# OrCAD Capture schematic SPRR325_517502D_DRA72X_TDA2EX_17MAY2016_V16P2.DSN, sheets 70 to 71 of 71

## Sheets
70 SH28 - MUX A/C QSPI/EMMC/GPMX: size B; rev: A
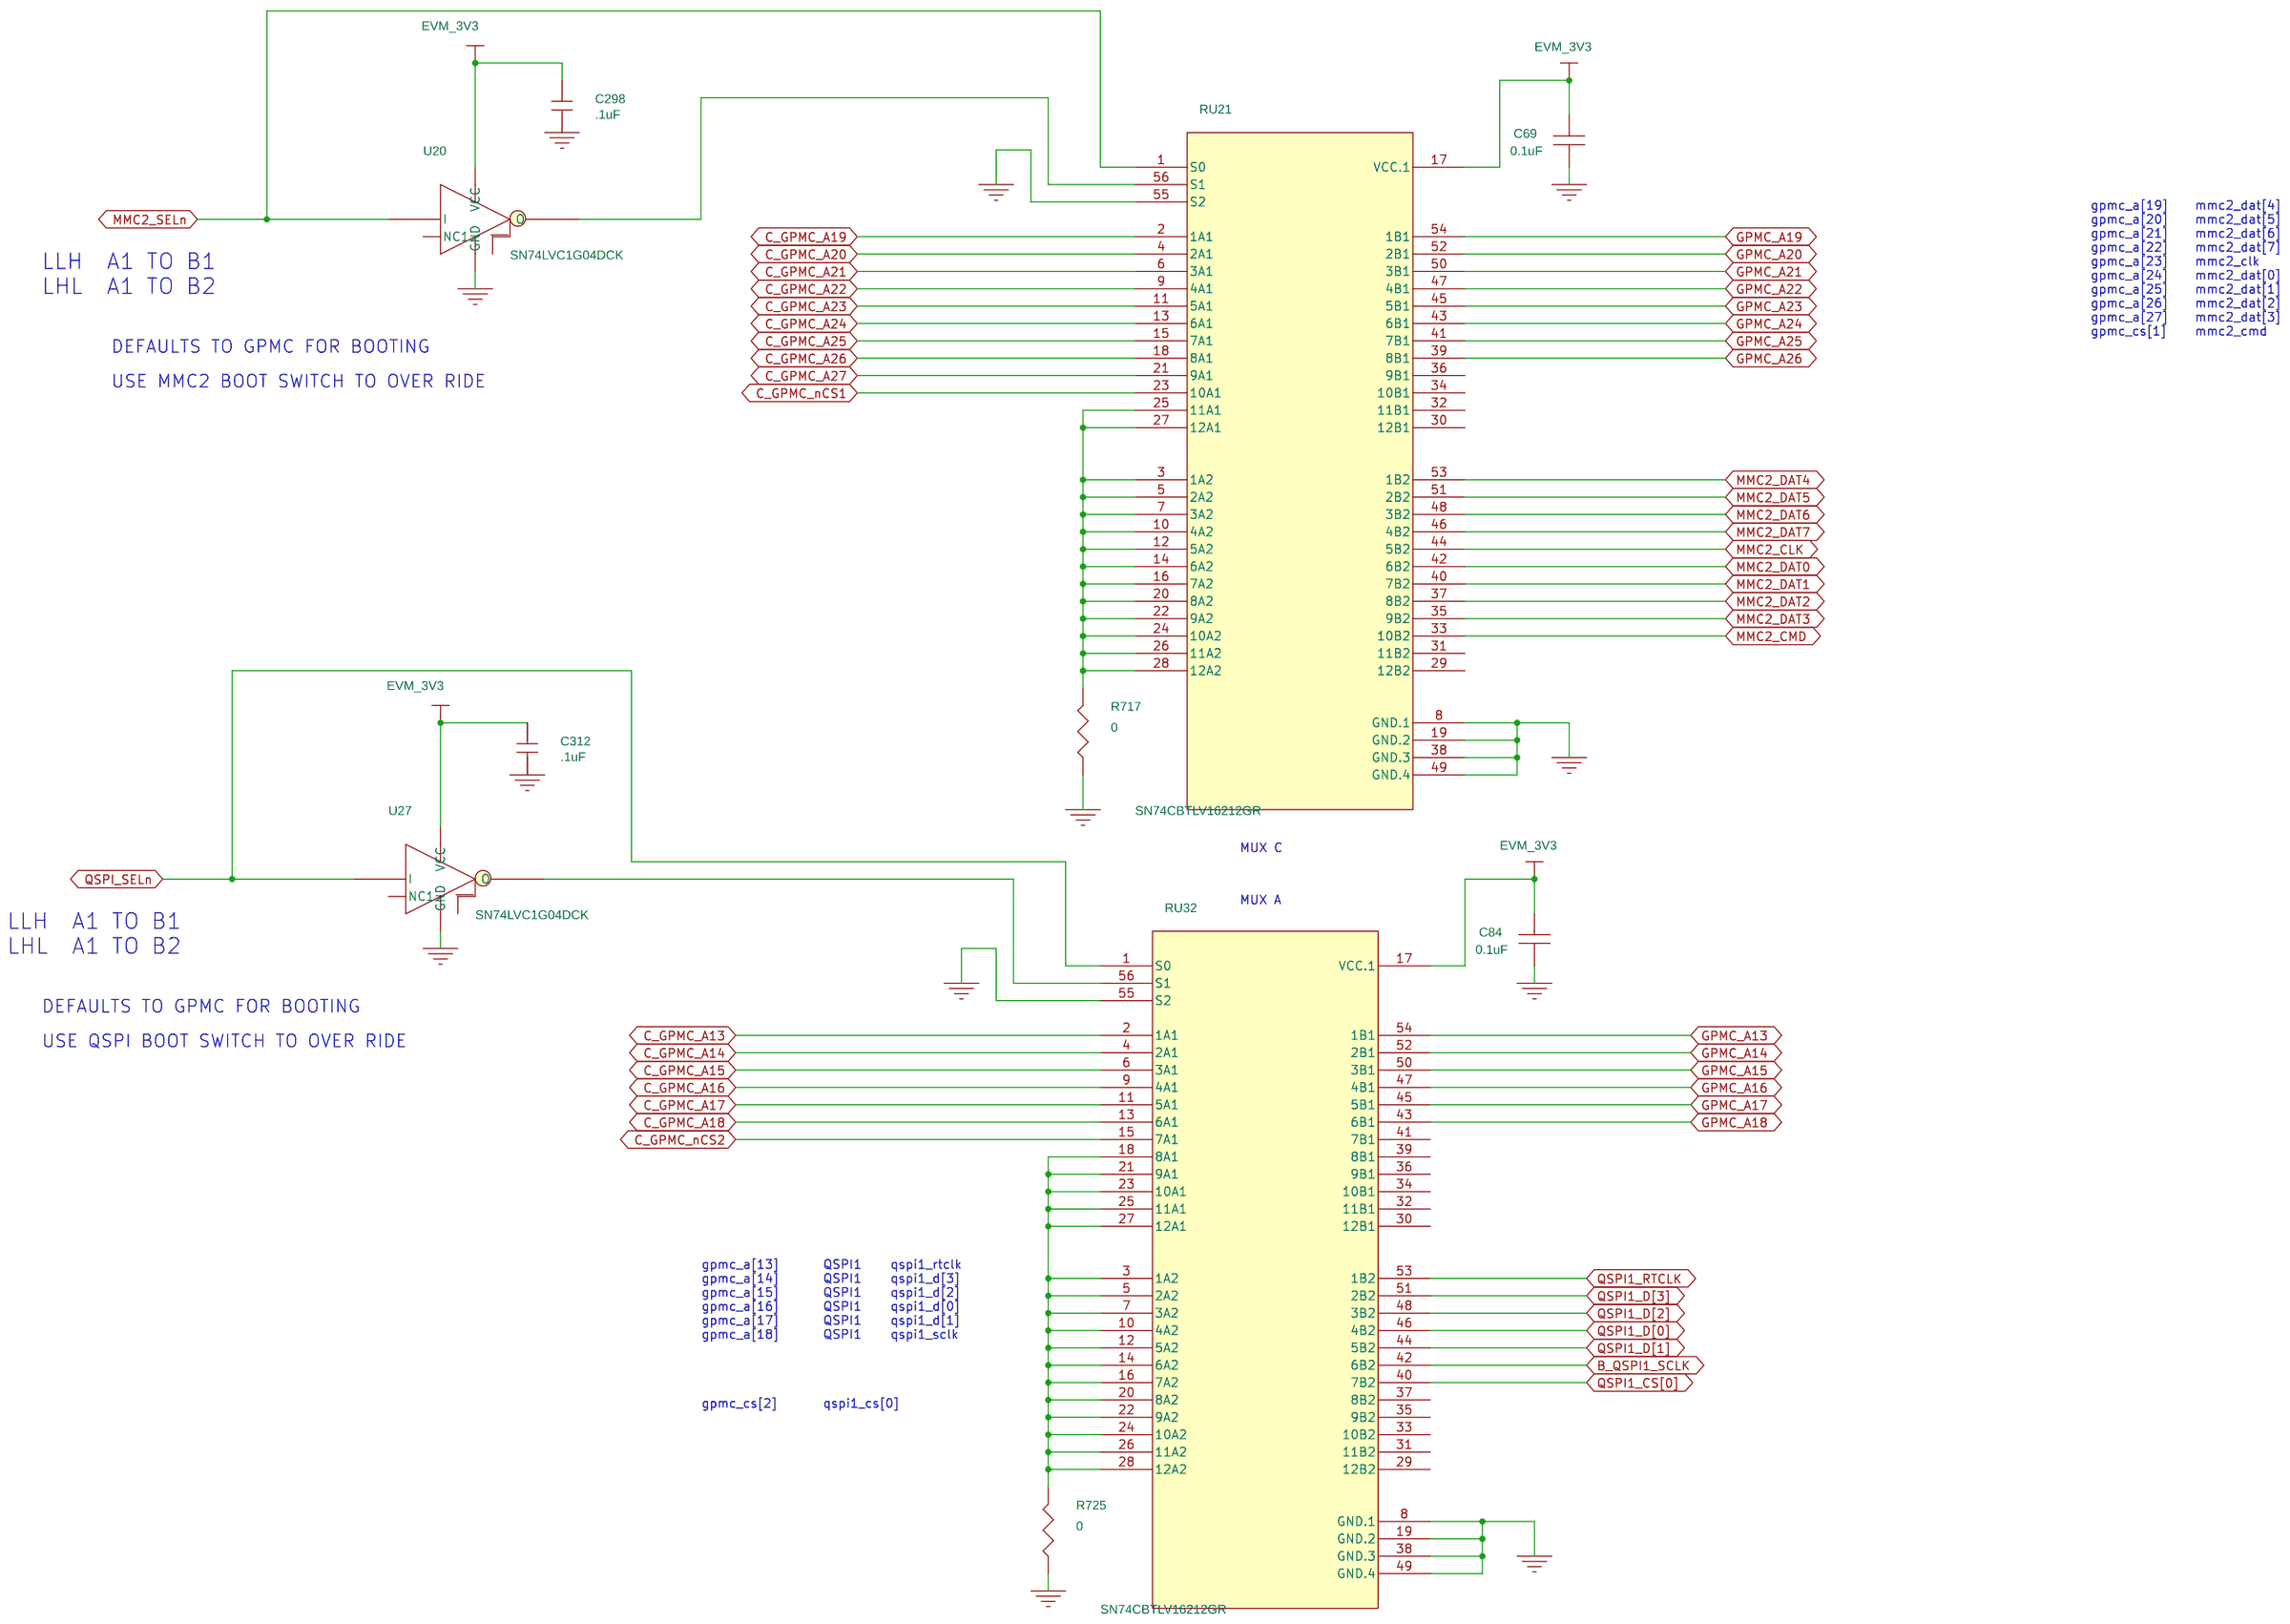
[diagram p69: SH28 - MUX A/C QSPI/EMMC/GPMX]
71 SH13 - SoC SATA/PCIe INTERFACE: size B; rev: C
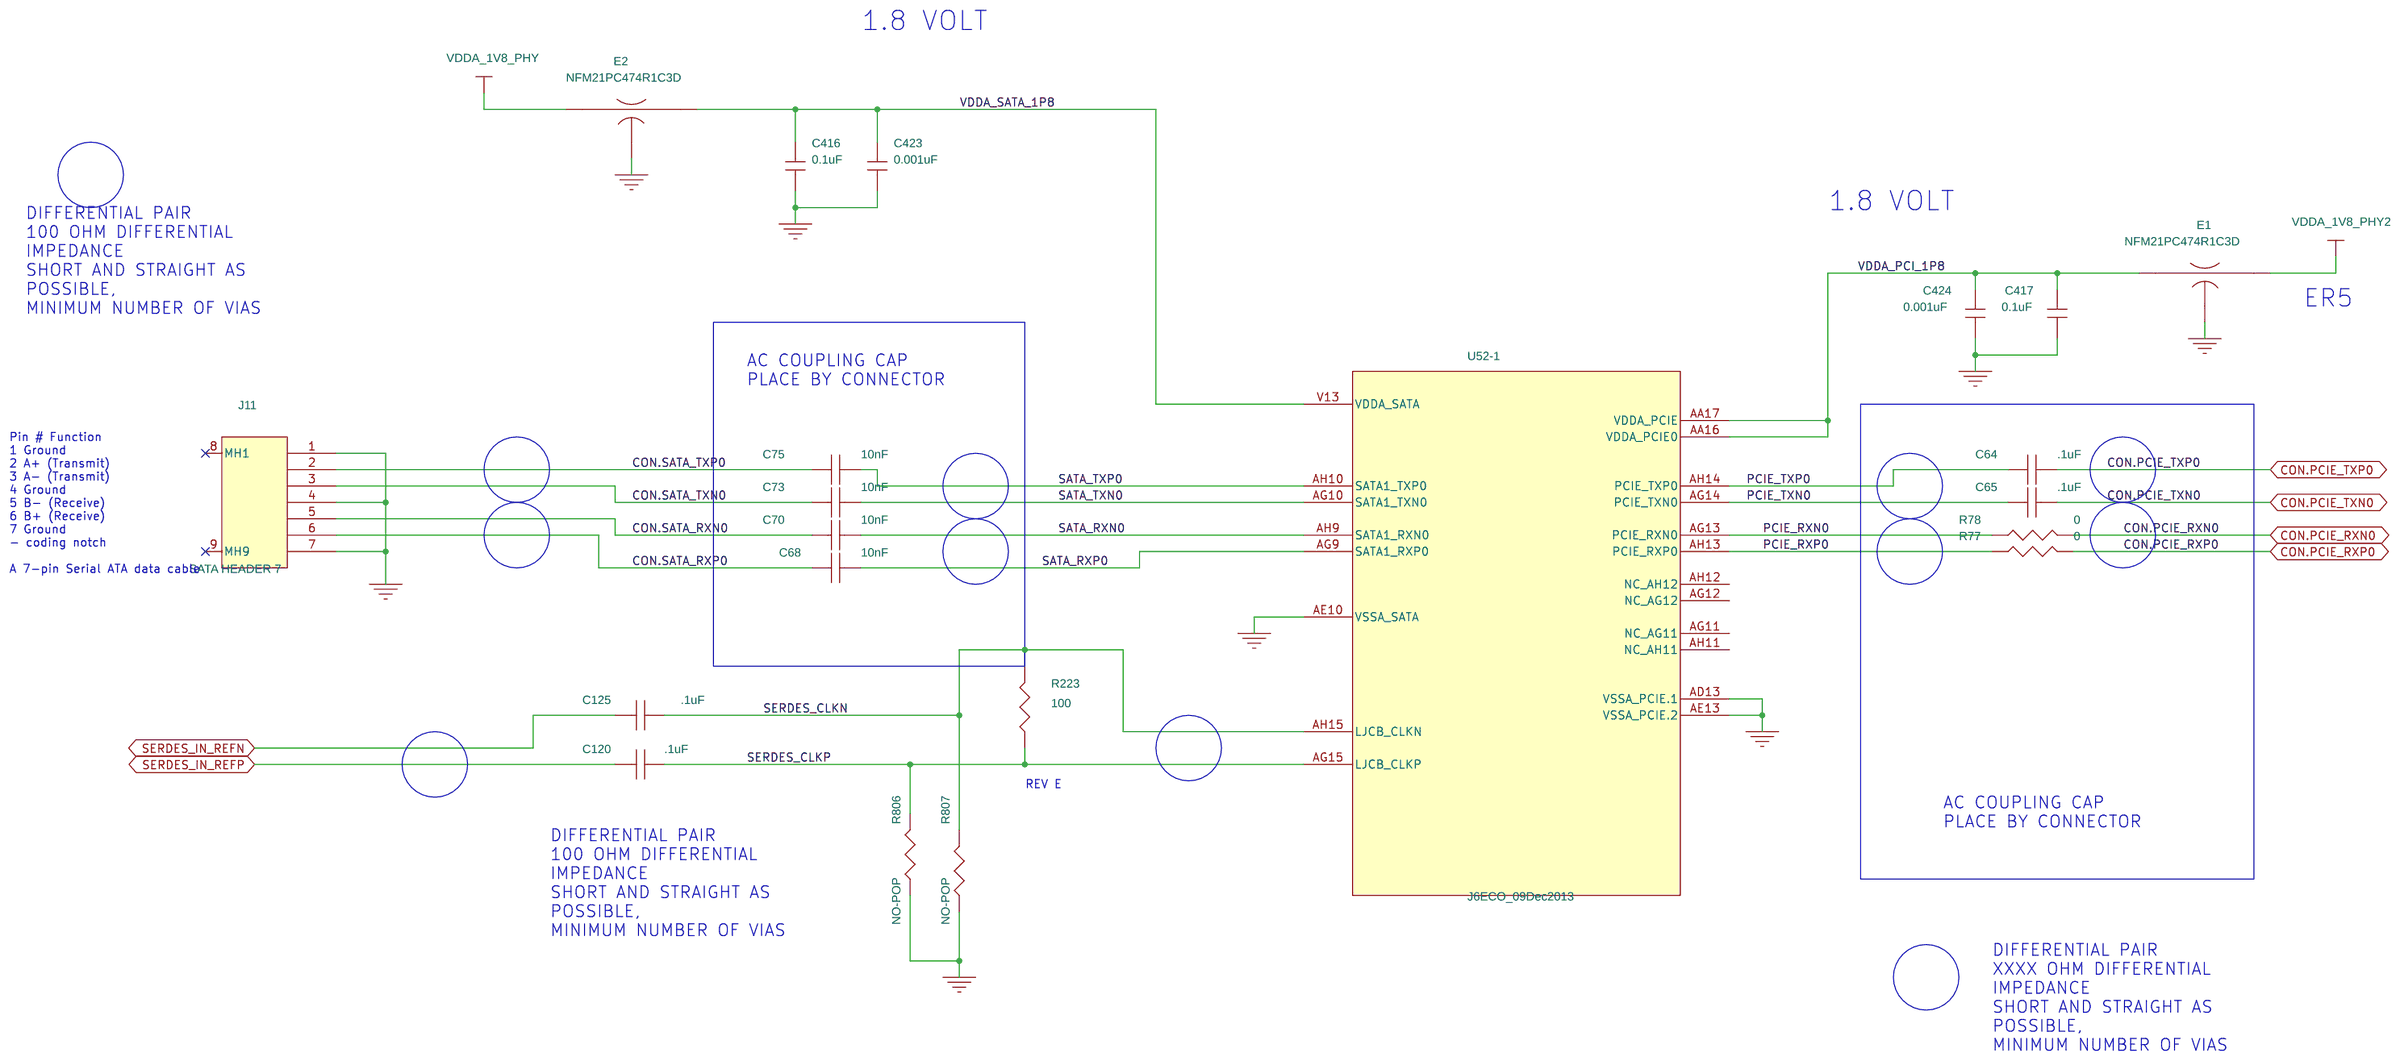
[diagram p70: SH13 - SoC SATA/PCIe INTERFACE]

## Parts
sheet SH13 - SoC SATA/PCIe INTERFACE
C64  .1uF  [c402-25]
C65  .1uF  [c402-25]
C68  10nF  [c402-25]
C70  10nF  [c402-25]
C73  10nF  [c402-25]
C75  10nF  [c402-25]
C120  .1uF  [c603-35x45]
C125  .1uF  [c603-35x45]
C416  0.1uF  [c201-18p5x15]
C417  0.1uF  [c201-18p5x15]
C423  0.001uF  [c201-18p5x15]
C424  0.001uF  [c201-18p5x15]
E1  NFM21PC474R1C3D  [emi-NFM21p]
E2  NFM21PC474R1C3D  [emi-NFM21p]
J11  SATA HEADER 7  [molex-67491-002]
R77  0  [r402-25]
R78  0  [r402-25]
R223  100  [r402-25]
R806  NO-POP  [r201-6p6spc]
R807  NO-POP  [r201-6p6spc]
sheet SH17 - SoC IO POWER
U52  J6ECO_09Dec2013  [sktbga-zkk-6334-p760]  (sections -1,-10,-11,-12,-13,-14,-15,-16,-17,-18,-19,-2,-20,-21,-22,-23,-3,-4,-5,-6,-7,-8,-9)
sheet SH28 - MUX A/C QSPI/EMMC/GPMX
C69  0.1uF  [c402-25]
C84  0.1uF  [c402-25]
C298  .1uF  [c402-25]
C312  .1uF  [c402-25]
R717  0  [r201-6p6spc]
R725  0  [r201-6p6spc]
RU21  SN74CBTLV16212GR  [dgg56-12x80]
RU32  SN74CBTLV16212GR  [dgg56-12x80]
U20  SN74LVC1G04DCK  [dck-5]
U27  SN74LVC1G04DCK  [dck-5]

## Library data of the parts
C64 C65 = CAP_.1_uF_10%_0603: Part #: 101587-1100R
C68 C70 C73 C75 = CAP_.1_uF_10%_0603: Part #: 101587-1101R
C120 C125 = CAP_.1_uF_10%_0603: Part #: 100994-1100R
C416 C417 = CAP_NP: Part #: 103241-1100R
C423 C424 = CAP_NP: Part #: 103367-1102R
E1 E2 = NFM_1: Part #: 102569-1470R
J11 = HEADER_7_0: Part #: 102930-0007R
R77 R78 = R: Part #: 101370-0001R
R223 = R: Part #: 101370-1001R
R806 R807 = R: Part #: R0201-NOPOP
U52 = J6ECO_RevC_0: Part #: 104492-0002R-TI
C69 C84 = CAP: Part #: 101587-1100R
C298 C312 = CAP_NP: Part #: 101587-1100R
R717 R725 = R: Part #: 103158-0001R
RU21 RU32 = SN74CBT16212DGGR_0: Part #: 102693-0001R
U20 U27 = SN74LVC1GU04_1: Part #: 101057-0004R

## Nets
GND: C69.2 C84.2 C298.2 C312.2 C416.2 C417.2 C423.2 C424.2 E1.2 E2.2 J11.1 J11.4 J11.7 R717.1 R725.1 R806.2 R807.2 RU21.8(GND.1) RU21.19(GND.2) RU21.38(GND.3) RU21.49(GND.4) RU21.55(S2) RU32.8(GND.1) RU32.19(GND.2) RU32.38(GND.3) RU32.49(GND.4) RU32.55(S2) U20.3(GND) U27.3(GND) U52.AD13(VSSA_PCIE.1) U52.AE10(VSSA_SATA) U52.AE13(VSSA_PCIE.2) ; also on sheet 3 5 7 10 11 12 13 14 15 16 17 18 20 21 22 23 24 25 26 27 28 29 30 31 32 33 34 35 36 37 38 39 40 41 42 43 44 45 46 47 48 49 50 51 52 53 54 55 56 57 58 59 62 63 64 65 66 67 68 69
VDDA_1V8_PHY2: E1.3 ; also on sheet 7 58 64
VDDA_PCI_1P8: C417.1 C424.1 E1.1 U52.AA16(VDDA_PCIE0) U52.AA17(VDDA_PCIE)
VDDA_SATA_1P8: C416.1 C423.1 E2.1 U52.V13(VDDA_SATA)
B_QSPI1_SCLK: RU32.42(6B2) ; also on sheet 26
C_GPMC_A13: RU32.2(1A1) ; also on sheet 4
C_GPMC_A14: RU32.4(2A1) ; also on sheet 4
C_GPMC_A15: RU32.6(3A1) ; also on sheet 4
C_GPMC_A16: RU32.9(4A1) ; also on sheet 4
C_GPMC_A17: RU32.11(5A1) ; also on sheet 4
C_GPMC_A18: RU32.13(6A1) ; also on sheet 4
C_GPMC_A19: RU21.2(1A1) ; also on sheet 4
C_GPMC_A20: RU21.4(2A1) ; also on sheet 4
C_GPMC_A21: RU21.6(3A1) ; also on sheet 4
C_GPMC_A22: RU21.9(4A1) ; also on sheet 4
C_GPMC_A23: RU21.11(5A1) ; also on sheet 4
C_GPMC_A24: RU21.13(6A1) ; also on sheet 4
C_GPMC_A25: RU21.15(7A1) ; also on sheet 4
C_GPMC_A26: RU21.18(8A1) ; also on sheet 4
C_GPMC_A27: RU21.21(9A1) ; also on sheet 4
C_GPMC_nCS1: RU21.23(10A1) ; also on sheet 4
C_GPMC_nCS2: RU32.15(7A1) ; also on sheet 4 24
CON.PCIE_RXN0: R78.2 ; also on sheet 36
CON.PCIE_RXP0: R77.2 ; also on sheet 36
CON.PCIE_TXN0: C65.2 ; also on sheet 36
CON.PCIE_TXP0: C64.2 ; also on sheet 36
CON.SATA_RXN0: C70.1 J11.5
CON.SATA_RXP0: C68.1 J11.6
CON.SATA_TXN0: C73.1 J11.3
CON.SATA_TXP0: C75.1 J11.2
EVM_3V3: C69.1 C84.1 C298.1 C312.1 RU21.17(VCC.1) RU32.17(VCC.1) U20.5(VCC) U27.5(VCC) ; also on sheet 3 4 10 11 24 25 26 27 28 29 30 31 32 33 34 35 36 37 38 39 40 42 43 44 45 46 47 48 49 50 51 55 56 58 59 62 63 65 66 67 69
GPMC_A13: RU32.54(1B1) ; also on sheet 28
GPMC_A14: RU32.52(2B1) ; also on sheet 28
GPMC_A15: RU32.50(3B1) ; also on sheet 28
GPMC_A16: RU32.47(4B1) ; also on sheet 28
GPMC_A17: RU32.45(5B1) ; also on sheet 28
GPMC_A18: RU32.43(6B1) ; also on sheet 28
GPMC_A19: RU21.54(1B1) ; also on sheet 24
GPMC_A20: RU21.52(2B1) ; also on sheet 24
GPMC_A21: RU21.50(3B1) ; also on sheet 24
GPMC_A22: RU21.47(4B1) ; also on sheet 24
GPMC_A23: RU21.45(5B1) ; also on sheet 24
GPMC_A24: RU21.43(6B1) ; also on sheet 24
GPMC_A25: RU21.41(7B1) ; also on sheet 24
GPMC_A26: RU21.39(8B1) ; also on sheet 24
J6_VDDA_PHY: E2.3 ; also on sheet 16 58 64
MMC2_CLK: RU21.44(5B2) ; also on sheet 29
MMC2_CMD: RU21.33(10B2) ; also on sheet 29
MMC2_DAT0: RU21.42(6B2) ; also on sheet 29
MMC2_DAT1: RU21.40(7B2) ; also on sheet 29
MMC2_DAT2: RU21.37(8B2) ; also on sheet 29
MMC2_DAT3: RU21.35(9B2) ; also on sheet 29
MMC2_DAT4: RU21.53(1B2) ; also on sheet 29
MMC2_DAT5: RU21.51(2B2) ; also on sheet 29
MMC2_DAT6: RU21.48(3B2) ; also on sheet 29
MMC2_DAT7: RU21.46(4B2) ; also on sheet 29
MMC2_SELn: RU21.1(S0) U20.2(I) ; also on sheet 13 42 43
PCIE_RXN0: R78.1 U52.AG13(PCIE_RXN0)
PCIE_RXP0: R77.1 U52.AH13(PCIE_RXP0)
PCIE_TXN0: C65.1 U52.AG14(PCIE_TXN0)
PCIE_TXP0: C64.1 U52.AH14(PCIE_TXP0)
QSPI1_CS[0]: RU32.40(7B2) ; also on sheet 26
QSPI1_D[0]: RU32.46(4B2) ; also on sheet 26
QSPI1_D[1]: RU32.44(5B2) ; also on sheet 26
QSPI1_D[2]: RU32.48(3B2) ; also on sheet 26
QSPI1_D[3]: RU32.51(2B2) ; also on sheet 26
QSPI1_RTCLK: RU32.53(1B2) ; also on sheet 26
QSPI_SELn: RU32.1(S0) U27.2(I) ; also on sheet 42 43
SATA_RXN0: C70.2 U52.AH9(SATA1_RXN0)
SATA_RXP0: C68.2 U52.AG9(SATA1_RXP0)
SATA_TXN0: C73.2 U52.AG10(SATA1_TXN0)
SATA_TXP0: C75.2 U52.AH10(SATA1_TXP0)
SERDES_CLKN: C125.1 R223.2 R807.1 U52.AH15(LJCB_CLKN)
SERDES_CLKP: C120.1 R223.1 R806.1 U52.AG15(LJCB_CLKP)
SERDES_IN_REFN: C125.2 ; also on sheet 35
SERDES_IN_REFP: C120.2 ; also on sheet 35
N18148112: R717.2 RU21.3(1A2) RU21.5(2A2) RU21.7(3A2) RU21.10(4A2) RU21.12(5A2) RU21.14(6A2) RU21.16(7A2) RU21.20(8A2) RU21.22(9A2) RU21.24(10A2) RU21.25(11A1) RU21.26(11A2) RU21.27(12A1) RU21.28(12A2)
N18150924: R725.2 RU32.3(1A2) RU32.5(2A2) RU32.7(3A2) RU32.10(4A2) RU32.12(5A2) RU32.14(6A2) RU32.16(7A2) RU32.18(8A1) RU32.20(8A2) RU32.21(9A1) RU32.22(9A2) RU32.23(10A1) RU32.24(10A2) RU32.25(11A1) RU32.26(11A2) RU32.27(12A1) RU32.28(12A2)
N28760816: RU21.56(S1) U20.4(O)
N29190185: RU32.56(S1) U27.4(O)

Not connected (* = marked no-connect by the designer): J11 8(MH1)* 9(MH9)*; RU21 29(12B2) 30(12B1) 31(11B2) 32(11B1) 34(10B1) 36(9B1); RU32 29(12B2) 30(12B1) 31(11B2) 32(11B1) 33(10B2) 34(10B1) 35(9B2) 36(9B1) 37(8B2) 39(8B1) 41(7B1); U20 1(NC1); U27 1(NC1); U52 AG11(NC) AG12(NC) AH11(NC) AH12(NC)

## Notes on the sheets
sheet 70
- gpmc_a[19]
  gpmc_a[20]
  gpmc_a[21]
  gpmc_a[22]
  gpmc_a[23]
  gpmc_a[24]
  gpmc_a[25]
  gpmc_a[26]
  gpmc_a[27]
  gpmc_cs[1]
- mmc2_dat[4]
  mmc2_dat[5]
  mmc2_dat[6]
  mmc2_dat[7]
  mmc2_clk
  mmc2_dat[0]
  mmc2_dat[1]
  mmc2_dat[2]
  mmc2_dat[3]
  mmc2_cmd
- LLH  A1 TO B1
  LHL  A1 TO B2
- DEFAULTS TO GPMC FOR BOOTING
- USE MMC2 BOOT SWITCH TO OVER RIDE
- MUX C
- MUX A
- LLH  A1 TO B1
  LHL  A1 TO B2
- DEFAULTS TO GPMC FOR BOOTING
- USE QSPI BOOT SWITCH TO OVER RIDE
- gpmc_a[13]
  gpmc_a[14]
  gpmc_a[15]
  gpmc_a[16]
  gpmc_a[17]
  gpmc_a[18]
- QSPI1	qspi1_rtclk
  QSPI1	qspi1_d[3]
  QSPI1	qspi1_d[2]
  QSPI1	qspi1_d[0]
  QSPI1	qspi1_d[1]
  QSPI1	qspi1_sclk
- gpmc_cs[2]
- qspi1_cs[0]
sheet 71
- 1.8 VOLT
- 1.8 VOLT
- DIFFERENTIAL PAIR
  100 OHM DIFFERENTIAL
  IMPEDANCE
  SHORT AND STRAIGHT AS
  POSSIBLE,
  MINIMUM NUMBER OF VIAS
- ER5
- AC COUPLING CAP
  PLACE BY CONNECTOR
- Pin # Function
  1 Ground
  2 A+ (Transmit)
  3 A- (Transmit)
  4 Ground
  5 B- (Receive)
  6 B+ (Receive)
  7 Ground
  - coding notch
  A 7-pin Serial ATA data cable
- REV E
- AC COUPLING CAP
  PLACE BY CONNECTOR
- DIFFERENTIAL PAIR
  100 OHM DIFFERENTIAL
  IMPEDANCE
  SHORT AND STRAIGHT AS
  POSSIBLE,
  MINIMUM NUMBER OF VIAS
- DIFFERENTIAL PAIR
  XXXX OHM DIFFERENTIAL
  IMPEDANCE
  SHORT AND STRAIGHT AS
  POSSIBLE,
  MINIMUM NUMBER OF VIAS
